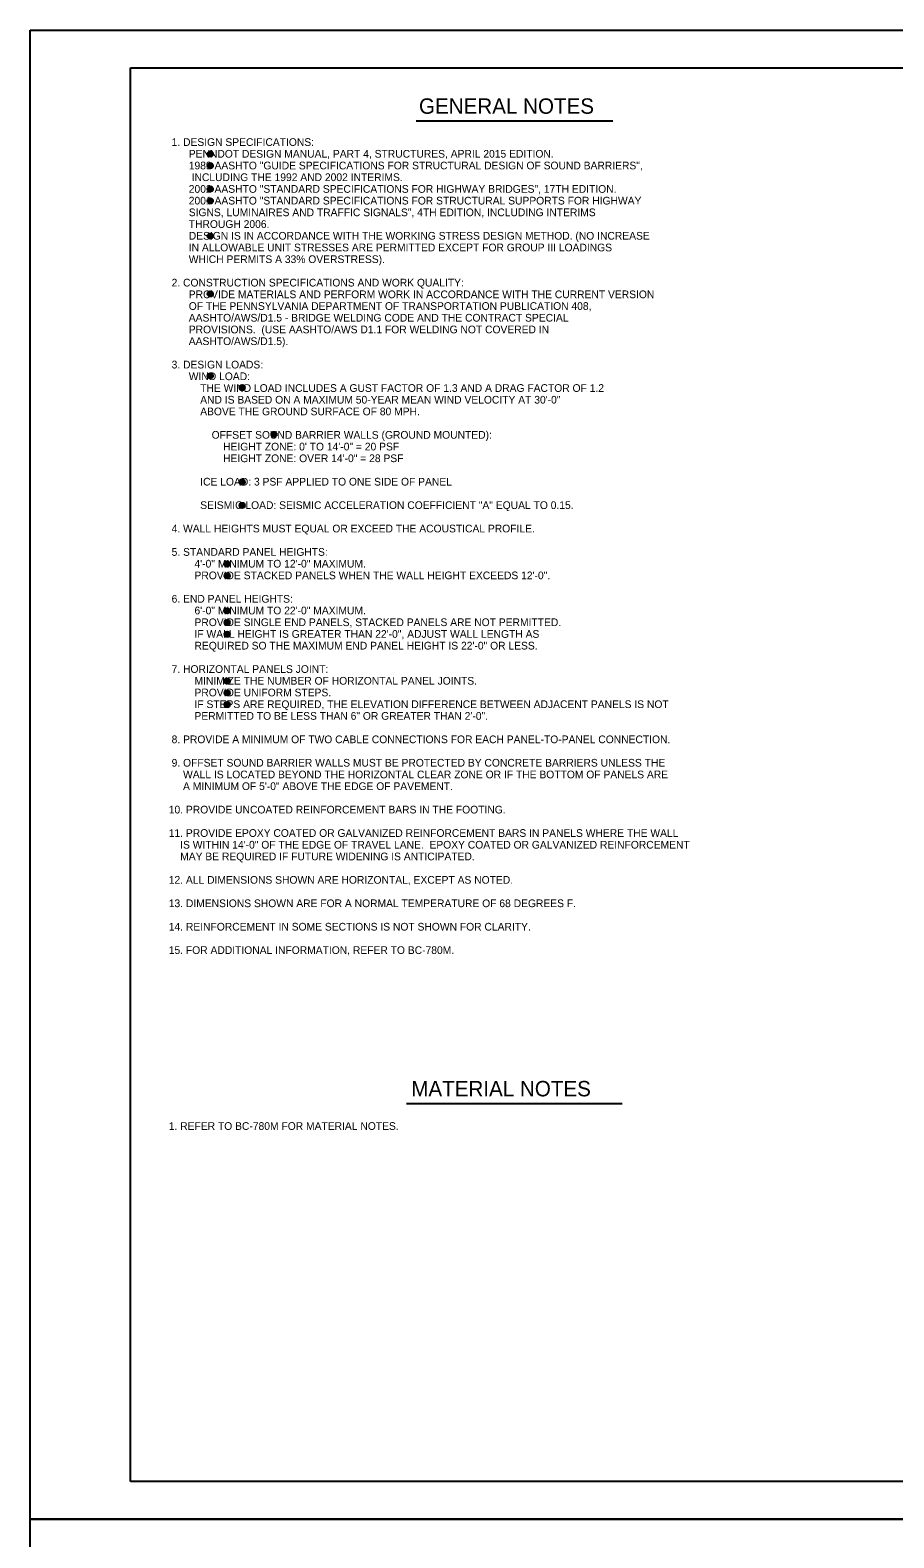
# Model space of a CAD drawing. Extents: x 3385 to 6532, y -616 to 1166.
# Drawn here: x 3761 to 4106, y 564 to 1166 of the extents above; entities that cross this region are included whole.
import ezdxf

# ---------------------------------------------------------------- set-up
doc = ezdxf.new("R2010")
doc.units = 0
for name, color, linetype in [('1', 7, 'Continuous'), ('2', 7, 'Continuous'), ('PLT-BNDY', 7, 'Continuous')]:
    doc.layers.add(name, color=color, linetype=linetype)

msp = doc.modelspace()

# ---------------------------------------------------------------- linework, layer by layer
at = {"layer": '1'}
for p, q in [((3915.34, 1129.45), (3993.92, 1129.45)), ((3911.57, 737.44), (3997.54, 737.44))]:
    msp.add_line(p, q, dxfattribs=at)
for centre, radius in [((3833.22, 1116.29), 1.07), ((3833.22, 1116.29), 0.8), ((3833.22, 1116.29), 0.533), ((3833.22, 1116.29), 0.267), ((3833.22, 1111.61), 1.07), ((3833.22, 1111.61), 0.8), ((3833.22, 1111.61), 0.533), ((3833.22, 1111.61), 0.267), ((3833.22, 1102.27), 1.07), ((3833.22, 1102.27), 0.8), ((3833.22, 1102.27), 0.533), ((3833.22, 1102.27), 0.267), ((3833.22, 1097.55), 1.07), ((3833.22, 1097.55), 0.8), ((3833.22, 1097.55), 0.533), ((3833.22, 1097.55), 0.267), ((3833.22, 1083.53), 1.07), ((3833.22, 1083.53), 0.8), ((3833.22, 1083.53), 0.533), ((3833.22, 1083.53), 0.267), ((3833.22, 1060.48), 1.07), ((3833.22, 1060.48), 0.8), ((3833.22, 1060.48), 0.533), ((3833.22, 1060.48), 0.267), ((3833.22, 1027.78), 1.07), ((3833.22, 1027.78), 0.8), ((3833.22, 1027.78), 0.533), ((3833.22, 1027.78), 0.267), ((3845.96, 1023.1), 1.07), ((3845.96, 1023.1), 0.8), ((3845.96, 1023.1), 0.533), ((3845.96, 1023.1), 0.267), ((3858.69, 1004.42), 1.07), ((3858.69, 1004.42), 0.8), ((3858.69, 1004.42), 0.533), ((3858.69, 1004.42), 0.267), ((3845.96, 985.41), 1.07), ((3845.96, 985.41), 0.8), ((3845.96, 985.41), 0.533), ((3845.96, 985.41), 0.267), ((3845.96, 976.07), 1.07), ((3845.96, 976.07), 0.8), ((3845.96, 976.07), 0.533), ((3845.96, 976.07), 0.267), ((3839.96, 952.71), 1.07), ((3839.96, 952.71), 0.8), ((3839.96, 952.71), 0.533), ((3839.96, 952.71), 0.267), ((3839.96, 948.04), 1.07), ((3839.96, 948.04), 0.8), ((3839.96, 948.04), 0.533), ((3839.96, 948.04), 0.267), ((3839.96, 934.02), 1.07), ((3839.96, 934.02), 0.8), ((3839.96, 934.02), 0.533), ((3839.96, 934.02), 0.267), ((3839.96, 929.35), 1.07), ((3839.96, 929.35), 0.8), ((3839.96, 929.35), 0.533), ((3839.96, 929.35), 0.267), ((3839.96, 924.68), 1.07), ((3839.96, 924.68), 0.8), ((3839.96, 924.68), 0.533), ((3839.96, 924.68), 0.267), ((3839.96, 905.99), 1.07), ((3839.96, 901.32), 1.07), ((3839.96, 905.99), 0.8), ((3839.96, 905.99), 0.533), ((3839.96, 905.99), 0.267), ((3839.96, 896.64), 1.07), ((3839.96, 901.32), 0.8), ((3839.96, 896.64), 0.8), ((3839.96, 901.32), 0.533), ((3839.96, 896.64), 0.533), ((3839.96, 901.32), 0.267), ((3839.96, 896.64), 0.267)]:
    msp.add_circle(centre, radius, dxfattribs=at)
at = {"layer": '2'}
for p, q in [((3801.34, 586.69), (3801.34, 1150.69)), ((3801.34, 1150.69), (4587.34, 1150.69)), ((4587.34, 586.69), (3801.34, 586.69))]:
    msp.add_line(p, q, dxfattribs=at)
at = {"layer": 'PLT-BNDY'}
for points in [[(3761.34, 1165.69), (4602.34, 1165.69), (4602.34, 571.69), (3761.34, 571.69)], [(3761.34, 571.69), (4602.34, 571.69), (4602.34, -22.31), (3761.34, -22.31)]]:
    msp.add_lwpolyline(points, close=True, dxfattribs=at)

# ---------------------------------------------------------------- texts
at = {"layer": '1'}
for s, height, p in [('GENERAL NOTES', 6.1441, (3916.51, 1132.33)), (' 1. DESIGN SPECIFICATIONS:', 3.072, (3816.65, 1119.5)), ('       1989 AASHTO "GUIDE SPECIFICATIONS FOR STRUCTURAL DESIGN OF SOUND BARRIERS",', 3.072, (3816.65, 1110.15)), ('       PENNDOT DESIGN MANUAL, PART 4, STRUCTURES, APRIL 2015 EDITION.', 3.072, (3816.65, 1114.83)), ('        INCLUDING THE 1992 AND 2002 INTERIMS.', 3.072, (3816.65, 1105.48)), ('       2002 AASHTO "STANDARD SPECIFICATIONS FOR HIGHWAY BRIDGES", 17TH EDITION.', 3.072, (3816.65, 1100.81)), ('       2001 AASHTO "STANDARD SPECIFICATIONS FOR STRUCTURAL SUPPORTS FOR HIGHWAY', 3.072, (3816.65, 1096.14)), ('       THROUGH 2006.', 3.072, (3816.65, 1086.79)), ('       SIGNS, LUMINAIRES AND TRAFFIC SIGNALS", 4TH EDITION, INCLUDING INTERIMS', 3.072, (3816.65, 1091.47)), ('       DESIGN IS IN ACCORDANCE WITH THE WORKING STRESS DESIGN METHOD. (NO INCREASE', 3.072, (3816.65, 1082.12)), ('       IN ALLOWABLE UNIT STRESSES ARE PERMITTED EXCEPT FOR GROUP III LOADINGS', 3.072, (3816.65, 1077.45)), ('       WHICH PERMITS A 33% OVERSTRESS).', 3.072, (3816.65, 1072.78)), (' 2. CONSTRUCTION SPECIFICATIONS AND WORK QUALITY:', 3.072, (3816.65, 1063.43)), ('       PROVIDE MATERIALS AND PERFORM WORK IN ACCORDANCE WITH THE CURRENT VERSION', 3.072, (3816.65, 1058.76)), ('       AASHTO/AWS/D1.5 - BRIDGE WELDING CODE AND THE CONTRACT SPECIAL', 3.072, (3816.65, 1049.42)), ('       OF THE PENNSYLVANIA DEPARTMENT OF TRANSPORTATION PUBLICATION 408,', 3.072, (3816.65, 1054.09)), ('       PROVISIONS.  (USE AASHTO/AWS D1.1 FOR WELDING NOT COVERED IN', 3.072, (3816.65, 1044.74)), ('       AASHTO/AWS/D1.5).', 3.072, (3816.65, 1040.07)), (' 3. DESIGN LOADS:', 3.072, (3816.65, 1030.73)), ('       WIND LOAD:', 3.072, (3816.65, 1026.06)), ('           THE WIND LOAD INCLUDES A GUST FACTOR OF 1.3 AND A DRAG FACTOR OF 1.2', 3.072, (3816.65, 1021.38)), ('           AND IS BASED ON A MAXIMUM 50-YEAR MEAN WIND VELOCITY AT 30\'-0"', 3.072, (3816.65, 1016.71)), ('           ABOVE THE GROUND SURFACE OF 80 MPH.', 3.072, (3816.65, 1012.04)), ('               OFFSET SOUND BARRIER WALLS (GROUND MOUNTED):', 3.072, (3816.65, 1002.7)), ('                   HEIGHT ZONE: 0\' TO 14\'-0" = 20 PSF', 3.072, (3816.65, 998.02)), ('                   HEIGHT ZONE: OVER 14\'-0" = 28 PSF', 3.072, (3816.65, 993.35)), ('           ICE LOAD: 3 PSF APPLIED TO ONE SIDE OF PANEL', 3.072, (3816.65, 984.01)), ('           SEISMIC LOAD: SEISMIC ACCELERATION COEFFICIENT "A" EQUAL TO 0.15.', 3.072, (3816.65, 974.66)), (' 4. WALL HEIGHTS MUST EQUAL OR EXCEED THE ACOUSTICAL PROFILE.', 3.072, (3816.65, 965.32)), (' 5. STANDARD PANEL HEIGHTS:', 3.072, (3816.65, 955.98)), ('         4\'-0" MINIMUM TO 12\'-0" MAXIMUM.', 3.072, (3816.65, 951.3)), ('         PROVIDE STACKED PANELS WHEN THE WALL HEIGHT EXCEEDS 12\'-0".', 3.072, (3816.65, 946.63)), (' 6. END PANEL HEIGHTS:', 3.072, (3816.65, 937.29)), ('         6\'-0" MINIMUM TO 22\'-0" MAXIMUM.', 3.072, (3816.65, 932.62)), ('         PROVIDE SINGLE END PANELS, STACKED PANELS ARE NOT PERMITTED.', 3.072, (3816.65, 927.94)), ('         IF WALL HEIGHT IS GREATER THAN 22\'-0", ADJUST WALL LENGTH AS', 3.072, (3816.65, 923.27)), ('         REQUIRED SO THE MAXIMUM END PANEL HEIGHT IS 22\'-0" OR LESS.', 3.072, (3816.65, 918.6)), (' 7. HORIZONTAL PANELS JOINT:', 3.072, (3816.65, 909.26)), ('         MINIMIZE THE NUMBER OF HORIZONTAL PANEL JOINTS.', 3.072, (3816.65, 904.58)), ('         PROVIDE UNIFORM STEPS.', 3.072, (3816.65, 899.91)), ('         IF STEPS ARE REQUIRED, THE ELEVATION DIFFERENCE BETWEEN ADJACENT PANELS IS NOT', 3.072, (3816.65, 895.24)), ('         PERMITTED TO BE LESS THAN 6" OR GREATER THAN 2\'-0".', 3.072, (3816.65, 890.57)), (' 8. PROVIDE A MINIMUM OF TWO CABLE CONNECTIONS FOR EACH PANEL-TO-PANEL CONNECTION.', 3.072, (3816.65, 881.22)), (' 9. OFFSET SOUND BARRIER WALLS MUST BE PROTECTED BY CONCRETE BARRIERS UNLESS THE', 3.072, (3816.65, 871.88)), ('     WALL IS LOCATED BEYOND THE HORIZONTAL CLEAR ZONE OR IF THE BOTTOM OF PANELS ARE', 3.072, (3816.65, 867.21)), ('     A MINIMUM OF 5\'-0" ABOVE THE EDGE OF PAVEMENT.', 3.072, (3816.65, 862.53)), ('10. PROVIDE UNCOATED REINFORCEMENT BARS IN THE FOOTING.', 3.072, (3816.65, 853.19)), ('11. PROVIDE EPOXY COATED OR GALVANIZED REINFORCEMENT BARS IN PANELS WHERE THE WALL', 3.072, (3816.65, 843.85)), ('    IS WITHIN 14\'-0" OF THE EDGE OF TRAVEL LANE.  EPOXY COATED OR GALVANIZED REINFORCEMENT', 3.072, (3816.65, 839.17)), ('    MAY BE REQUIRED IF FUTURE WIDENING IS ANTICIPATED.', 3.072, (3816.65, 834.5)), ('12. ALL DIMENSIONS SHOWN ARE HORIZONTAL, EXCEPT AS NOTED.', 3.072, (3816.65, 825.16)), ('13. DIMENSIONS SHOWN ARE FOR A NORMAL TEMPERATURE OF 68 DEGREES F.', 3.072, (3816.65, 815.81)), ('14. REINFORCEMENT IN SOME SECTIONS IS NOT SHOWN FOR CLARITY.', 3.072, (3816.65, 806.47)), ('15. FOR ADDITIONAL INFORMATION, REFER TO BC-780M.', 3.072, (3816.65, 797.13)), ('MATERIAL NOTES', 6.1441, (3913.43, 740.33)), ('1. REFER TO BC-780M FOR MATERIAL NOTES.', 3.072, (3816.65, 726.95))]:
    msp.add_text(s, height=height, dxfattribs=at).set_placement(p)

doc.saveas('drawing.dxf')
